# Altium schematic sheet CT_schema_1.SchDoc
size 611 x 349 mm
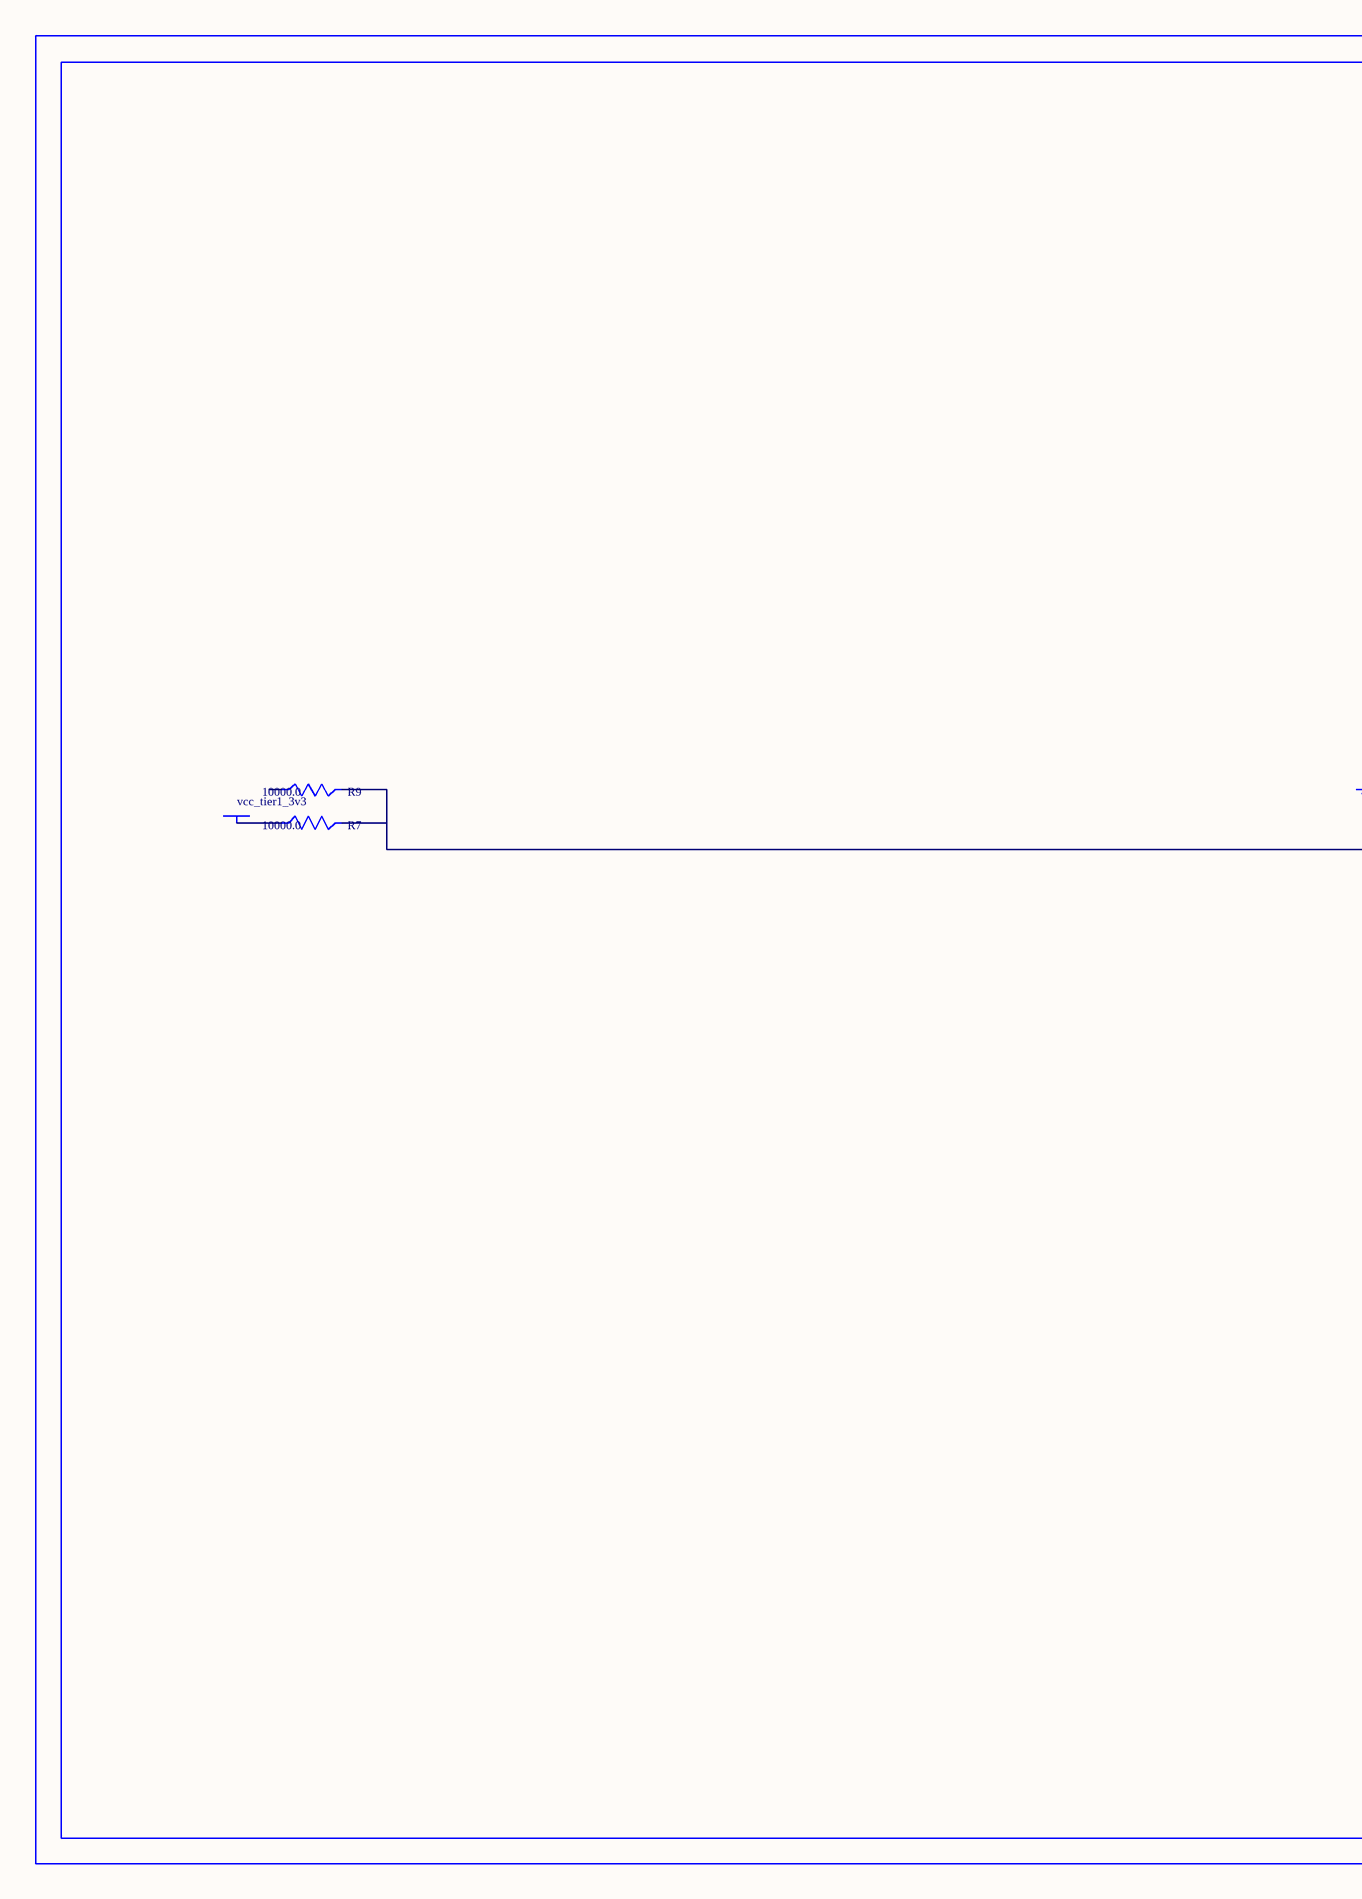
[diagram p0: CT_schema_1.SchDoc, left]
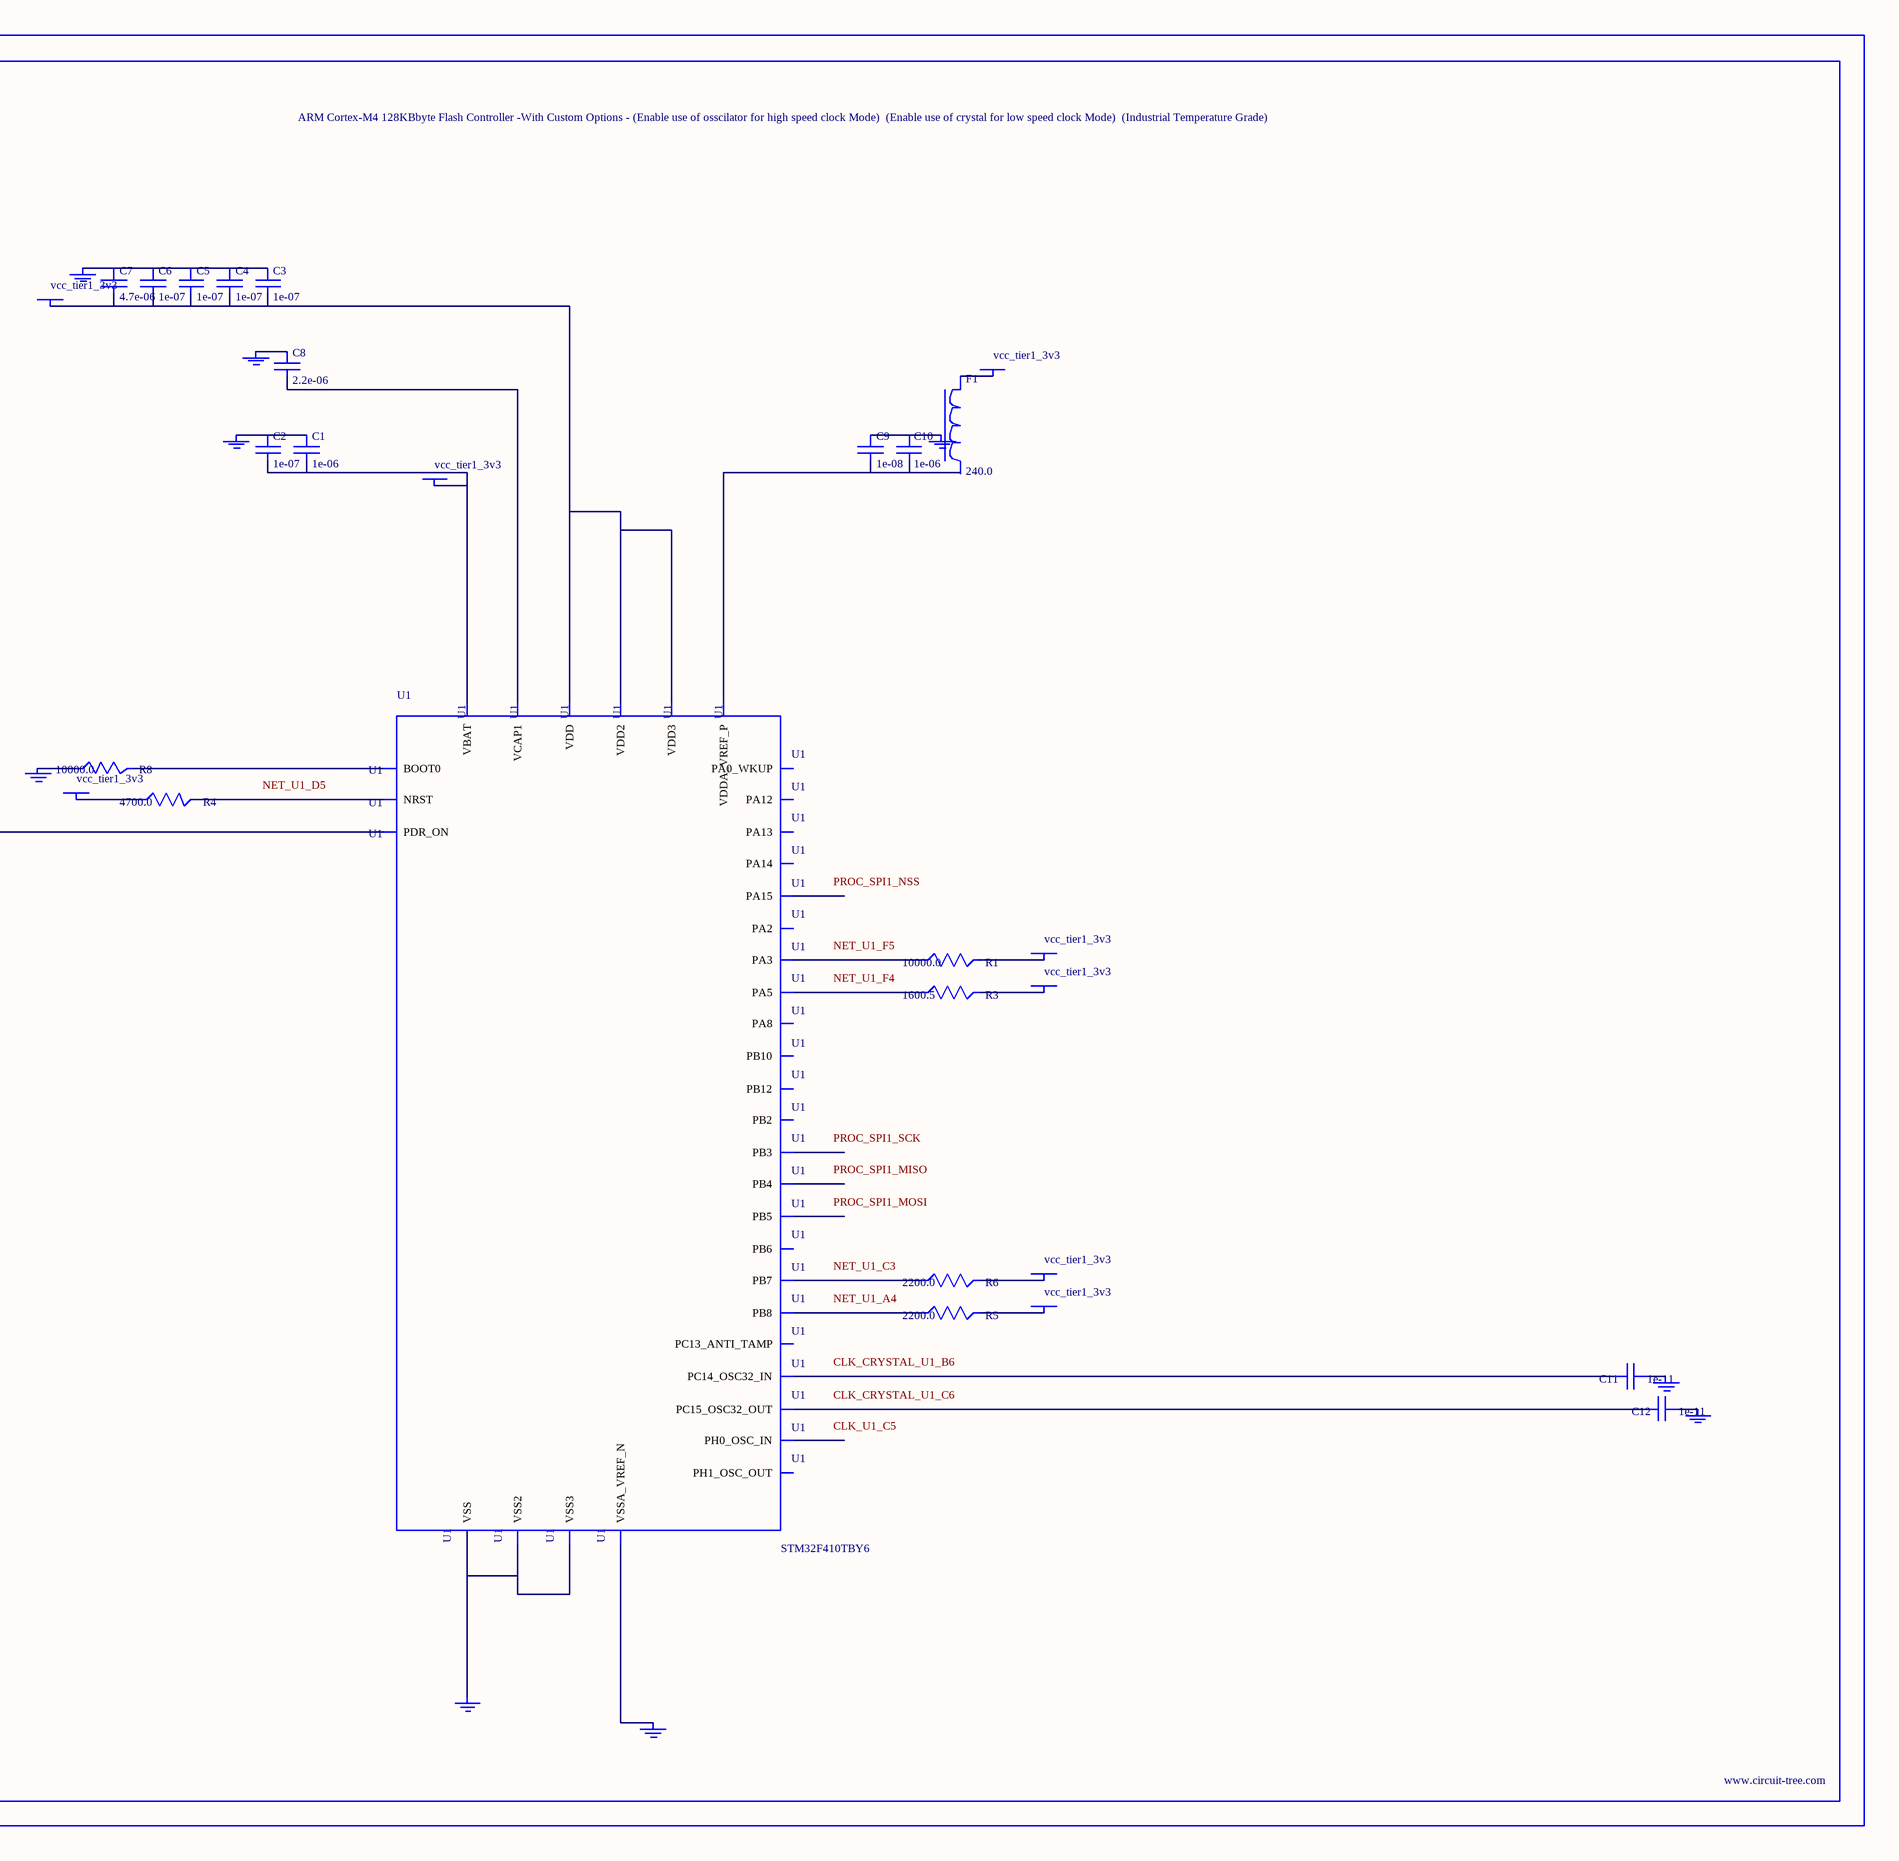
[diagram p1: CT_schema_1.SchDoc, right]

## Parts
BORDER0  (no value)
C1  1e-06  [C0603]
C2  1e-07  [C0603]
C3  1e-07  [C0603]
C4  1e-07  [C0603]
C5  1e-07  [C0603]
C6  1e-07  [C0603]
C7  4.7e-06  [C0603]
C8  2.2e-06  [C0603]
C9  1e-08  [C0603]
C10  1e-06  [C0603]
C11  1e-11  [C0402]
C12  1e-11  [C0402]
F1  240.0  [L0603]
GND_INSTANCE_0_0  (no value)
GND_INSTANCE_0_1  (no value)
GND_INSTANCE_0_2  (no value)
GND_INSTANCE_0_3  (no value)
GND_INSTANCE_0_4  (no value)
GND_INSTANCE_0_5  (no value)
GND_INSTANCE_0_6  (no value)
GND_INSTANCE_0_7  (no value)
GND_INSTANCE_0_8  (no value)
POWER_INSTANCE_0_0  vcc_tier1_3v3
POWER_INSTANCE_0_1  vcc_tier1_3v3
POWER_INSTANCE_0_2  vcc_tier1_3v3
POWER_INSTANCE_0_3  vcc_tier1_3v3
POWER_INSTANCE_0_4  vcc_tier1_3v3
POWER_INSTANCE_0_5  vcc_tier1_3v3
POWER_INSTANCE_0_6  vcc_tier1_3v3
POWER_INSTANCE_0_7  vcc_tier1_3v3
POWER_INSTANCE_0_8  vcc_tier1_3v3
R1  10000.0  [R0603]
R3  1600.5  [R0603]
R4  4700.0  [R0603]
R5  2200.0  [R0603]
R6  2200.0  [R0603]
R7  10000.0  [R0603]
R8  10000.0  [R0603]
R9  10000.0  [R0603]
U1  STM32F410TBY6  [WLCSP36]

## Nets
NetC1_1: C1.1 C2.1 GND_INSTANCE_0_0.0(GND)
NetC1_2: C1.2 C2.2 POWER_INSTANCE_0_0.0(PWR) U1.B5(VBAT)
NetC3_1: C3.1 C4.1 C5.1 C6.1 C7.1 GND_INSTANCE_0_2.0(GND)
NetC3_2: C3.2 C4.2 C5.2 C6.2 C7.2 POWER_INSTANCE_0_2.0(PWR) U1.A1(VDD) U1.A6(VDD2) U1.F1(VDD3)
NetC8_1: C8.1 GND_INSTANCE_0_4.0(GND)
NetC8_2: C8.2 U1.E2(VCAP1)
NetC9_1: C9.1 C10.1 GND_INSTANCE_0_1.0(GND)
NetC9_2: C9.2 C10.2 U1.F6(VDDA_VREF_P)
NetC11_1: C11.1 GND_INSTANCE_0_5.0(GND)
NetC11_2: C11.2 U1.B6(PC14_OSC32_IN)
NetC12_1: C12.1 GND_INSTANCE_0_6.0(GND)
NetC12_2: C12.2 U1.C6(PC15_OSC32_OUT)
NetF1_1: F1.1 POWER_INSTANCE_0_1.0(PWR)
NetGND_INSTANCE_0_3_0: GND_INSTANCE_0_3.0(GND) R8.1
NetGND_INSTANCE_0_7_0: GND_INSTANCE_0_7.0(GND) U1.E6(VSSA_VREF_N)
NetGND_INSTANCE_0_8_0: GND_INSTANCE_0_8.0(GND) U1.A5(VSS) U1.B1(VSS2) U1.F2(VSS3)
NetPOWER_INSTANCE_0_3_0: POWER_INSTANCE_0_3.0(PWR) R7.1
NetPOWER_INSTANCE_0_4_0: POWER_INSTANCE_0_4.0(PWR) R4.1
NetPOWER_INSTANCE_0_5_0: POWER_INSTANCE_0_5.0(PWR) R1.2
NetPOWER_INSTANCE_0_6_0: POWER_INSTANCE_0_6.0(PWR) R3.2
NetPOWER_INSTANCE_0_7_0: POWER_INSTANCE_0_7.0(PWR) R6.2
NetPOWER_INSTANCE_0_8_0: POWER_INSTANCE_0_8.0(PWR) R5.2
NetR1_1: R1.1 U1.F5(PA3)
NetR3_1: R3.1 U1.F4(PA5)
NetR4_2: R4.2 U1.D5(NRST)
NetR5_1: R5.1 U1.A4(PB8)
NetR6_1: R6.1 U1.C3(PB7)
NetR7_2: R7.2 R9.2 U1.B4(PDR_ON)
NetR8_2: R8.2 U1.D4(BOOT0)

Not connected (* = marked no-connect by the designer): F1 2; R9 1; U1 A2(PA15) A3(PB5) B2(PA14) B3(PB6) C1(PA13) C2(PB3) C4(PC13_ANTI_TAMP) C5(PH0_OSC_IN) D1(PA8) D2(PA12) D3(PB4) D6(PH1_OSC_OUT) E1(PB12) E3(PB10) E4(PA2) E5(PA0_WKUP) F3(PB2)

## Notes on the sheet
- Labels drawn without touching a wire or pin: CLK_CRYSTAL_U1_B6, CLK_CRYSTAL_U1_C6, CLK_U1_C5, NET_U1_A4, NET_U1_C3, NET_U1_D5, NET_U1_F4, NET_U1_F5, PROC_SPI1_MISO, PROC_SPI1_MOSI, PROC_SPI1_NSS, PROC_SPI1_SCK

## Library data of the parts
BORDER0 = BORDER_PAGE0
C1 C10 = C0603C105K3RACTU
C2-C6 = 06035C104K4Z2A
C7 = GRM188R6YA475KE15D
C8 = C0603C225K8RACTU
C9 = 06035C103K4Z2A
C11 C12 = C0402C100K3GACTU
F1 = Z0603C241ASMST
GND_INSTANCE_0_0-GND_INSTANCE_0_8 = GND
POWER_INSTANCE_0_0-POWER_INSTANCE_0_8 = PWR
R1 R7-R9 = RC0603JR-0710KL
R3 = R3
R4 = RC0603JR-074K7L
R5 R6 = RC0603JR-072K2L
